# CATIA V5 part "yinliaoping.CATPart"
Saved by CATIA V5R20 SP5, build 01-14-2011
Part number: 饮料瓶
Material "无"
Bounding box of the stored display mesh (mm): x -25 to 26, y -25 to 25, z 0 to 110
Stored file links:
  E:\3.8\yinliaop.CATPart
  C:\Program Files\Dassault Systemes\B20\intel_a\startup\materials\Catalog.CATMaterial
  C:\Program Files\Dassault Systemes\B20\intel_a\startup\materials\brushed_metal2.jpg
  C:\Program Files\Dassault Systemes\B20\intel_a\startup\materials\brushed_metal1.jpg
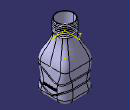
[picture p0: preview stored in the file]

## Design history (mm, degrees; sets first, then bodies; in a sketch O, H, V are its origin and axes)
Set1
  Sketch1 on xy-plane, origin (0, 0, 0), H (1, 0, 0), V (0, 1, 0)
    line L1 (25, 25) -> (25, -25)
    line L2 (25, -25) -> (-25, -25)
    line L3 (-25, -25) -> (-25, 25)
    line L4 (-25, 25) -> (25, 25)
    length L1 = 50
    length L4 = 50
    vertical: L1 V, L3 V
    horizontal: L2 H, L4 H
    equidistance: L1 L3 O, L2 L4 O
  Sketch2 on face of Pad1 from Sketch1.L1, origin (25, 0, 0), H (0, 1, 0), V (0, 0, 1)
    spline S1 through (-40, 10) (-20, 20) (0, 10) (20, 20) (40, 20)
    point P1 (0, 10)
    coincidence: P1 V
  Extrude1: Element1 Sketch2, Lim1 54, Lim2 54
  MultiSel1: CommonCtxFeats ({extract ExtractElem face of Pad1 from Sketch1.L3}; {extract ExtractElem face of Fillet1}; {extract ExtractElem face of Pad1 from Sketch1.L2}; {extract ExtractElem face of Fillet1}; {extract ExtractElem face of Pad1 from Sketch1.L1}; {extract ExtractElem face of Fillet1}; {extract ExtractElem face of Pad1 from Sketch1.L4}; {extract ExtractElem face of Fillet1})
  Sketch3 on face of Pad1 from Sketch1.L1, origin (25, 0, 0), H (0, 1, 0), V (0, 0, 1)
    spline S1 through (-50, 30) (-10, 40) (10, 30) (30, 40)
  Extrude2: Element1 Sketch3, Lim1 54, Lim2 54
  MultiSel2: CommonCtxFeats ({extract ExtractElem face of Fillet1}; {extract ExtractElem face of Pad1 from Sketch1.L3}; {extract ExtractElem face of Fillet1}; {extract ExtractElem face of Pad1 from Sketch1.L4}; {extract ExtractElem face of Fillet1}; {extract ExtractElem face of Pad1 from Sketch1.L1}; {extract ExtractElem face of Fillet1}; {extract ExtractElem face of Pad1 from Sketch1.L2})
  Join1: Elements ({intersect ToIntersect1 {extract ExtractElem face of Pad1 from Sketch1.L3}, ToIntersect2 Extrude1}; {intersect ToIntersect1 {extract ExtractElem face of Fillet1}, ToIntersect2 Extrude1}; {intersect ToIntersect1 {extract ExtractElem face of Pad1 from Sketch1.L2}, ToIntersect2 Extrude1}; {intersect ToIntersect1 {extract ExtractElem face of Fillet1}, ToIntersect2 Extrude1}; {intersect ToIntersect1 {extract ExtractElem face of Pad1 from Sketch1.L1}, ToIntersect2 Extrude1}; {intersect ToIntersect1 {extract ExtractElem face of Fillet1}, ToIntersect2 Extrude1}; {intersect ToIntersect1 {extract ExtractElem face of Pad1 from Sketch1.L4}, ToIntersect2 Extrude1}; {intersect ToIntersect1 {extract ExtractElem face of Fillet1}, ToIntersect2 Extrude1})
  Join2: Elements ({intersect ToIntersect1 {extract ExtractElem face of Fillet1}, ToIntersect2 Extrude2}; {intersect ToIntersect1 {extract ExtractElem face of Pad1 from Sketch1.L3}, ToIntersect2 Extrude2}; {intersect ToIntersect1 {extract ExtractElem face of Fillet1}, ToIntersect2 Extrude2}; {intersect ToIntersect1 {extract ExtractElem face of Pad1 from Sketch1.L4}, ToIntersect2 Extrude2}; {intersect ToIntersect1 {extract ExtractElem face of Fillet1}, ToIntersect2 Extrude2}; {intersect ToIntersect1 {extract ExtractElem face of Pad1 from Sketch1.L1}, ToIntersect2 Extrude2}; {intersect ToIntersect1 {extract ExtractElem face of Fillet1}, ToIntersect2 Extrude2}; {intersect ToIntersect1 {extract ExtractElem face of Pad1 from Sketch1.L2}, ToIntersect2 Extrude2})
  Plane1: type Normal, Curve Join1, RefPoint vertex [face of MultiSel1 | face of MultiSel1]
  Circle1: type CtrRad, Start 0, End 180, Center vertex [face of MultiSel1 | face of MultiSel1], Support Plane1, Radius 1, FirstDirection (1, 0, 0)
Body1 (main body), material "无"
  Pad1: profile Sketch1, direction (0, 0, 1), length 50
  Fillet1: on edge [face of Pad1 from Sketch1.L1 | face of Pad1 from Sketch1.L2]; edge [face of Pad1 from Sketch1.L2 | face of Pad1 from Sketch1.L3]; edge [face of Pad1 from Sketch1.L3 | face of Pad1 from Sketch1.L4]; edge [face of Pad1 from Sketch1.L4 | face of Pad1 from Sketch1.L1]
  Fillet2: radius 8, on edge [start face of Pad1 | face of Pad1 from Sketch1.L3]
  Plane2: type Offset, RefPlane end face of Pad1, Offset 40, reversed
  Sketch4 on Plane2, origin (0, 0, 90), H (1, 0, 0), V (0, -1, 0)
    circle A1 centre (0, 0) radius 15
  Pad2: profile Sketch4, direction (0, 0, 1), length 20
  Sketch5 on end face of Pad1, origin (0, 0, 50), H (1, 0, 0), V (0, 1, 0)
    point P1 (25, 0)
    distance P1 O = 25
    coincidence: P1 H
  Sketch6 on start face of Pad2, origin (0, 0, 90), H (1, 0, 0), V (0, -1, 0)
    point P1 (15, 0)
    distance P1 O = 15
    coincidence: P1 H
  Loft1: solid, Sections ({boundary Boundary {extract ExtractElem end face of Pad1}}; {boundary Boundary {extract ExtractElem start face of Pad2}}), StartFace end face of Pad1, EndFace start face of Pad2
  Slot1: profile Circle1, centre curve Join1
  Plane3: type Normal, Curve Join2, RefPoint vertex [face of MultiSel2 | face of MultiSel2]
  Circle2: type CtrRad, Start 0, End 180, Center vertex [face of MultiSel2 | face of MultiSel2], Support Plane3, Radius 1, FirstDirection (0, -1, 0)
  Slot2: profile Circle2, centre curve Join2
  Shell1: ExtOffset 0, Face end face of Pad2, IntOffset 1
  Plane4: type Offset, RefPlane xy-plane, Offset 91
  Sketch7 on Plane4, origin (0, 0, 91), H (1, 0, 0), V (0, 1, 0)
    point P1 (15, 0)
    distance P1 O = 15
    coincidence: P1 H
  Helix1: Direction Z axis, RefPoint Sketch7, Pitch 3, Height 16, TaperAngle 0
  Point1: type OnCurve, Support Helix1, RefPoint vertex of Helix1, Length -5
  Line1: type PtDir, RefPoint vertex of Helix1, Direction (0, 1, 0), Start 0, End -10
  Connect1: Curve1 Line1, Point1 vertex of Line1, Tension1 1, Curve2 Helix1, Point2 Point1, Tension2 1
  Point2: type OnCurve, Support Connect1, RefPoint Sketch7, Length -5
  Line2: type PtDir, RefPoint Sketch7, Direction (1, 0, 0), Start 0, End -10
  Connect2: Curve1 Line2, Point1 vertex of Line2, Tension1 1, Curve2 Connect1, Point2 Point2, Tension2 1
  Plane5: type Normal, Curve Connect2, RefPoint vertex of Connect1
  Circle3: type CtrRad, Start 0, End 180, Radius 1, Center vertex of Connect1, Support Plane5, FirstDirection (1, 0, 0)
  Rib1: profile Circle3, centre curve Connect2
  Sketch8 on {extract ExtractElem start face of Pad2}, origin (0, 0, 90), H (1, 0, 0), V (0, 1, 0)
  Body2
    Sketch9 on Plane4, origin (0, 0, 91), H (1, 0, 0), V (0, 1, 0)
      circle A1 centre (0, 0) radius 14
      radius A1 = 14
    Pad3: profile Sketch9, direction (0, 0, 1), length 20, mirrored extent
  Remove1: tool Body2
Body3
  Sketch10 on face of Pad1 from Sketch1.L1, origin (25, 0, 0), H (0, 1, 0), V (0, 0, 1)
    polyline C1
    polyline C2
    polyline C3
    polyline C4
    polyline C5
    polyline C6
    polyline C7
    polyline C8
    polyline C9
    polyline C10
    polyline C11
  Pad4: profile Sketch10, direction (1, 0, 0), length 1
